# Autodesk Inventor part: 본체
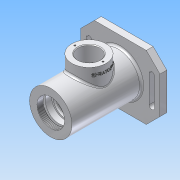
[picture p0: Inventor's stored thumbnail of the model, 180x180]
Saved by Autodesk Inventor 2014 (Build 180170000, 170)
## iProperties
Created: 2017-10
Part Number: 본체
Material: 알루미늄 6061
Document SubType Name: Modeling
Designer: user
Density: 2.71 g/cm^3
Appearance: 알루미늄 - 평지
Mass: 740.903 g
Surface Area: 653.463 cm^2
Volume: 273.396 cm^3
Author: user
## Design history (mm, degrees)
sketch "스케치1"
  geometry: C1 r 31 at (0, 0); 1 further point
  constraints: 1 centre point, 1 coincident
  dimensions: "d0" = 62 diameter of C1
extrude "돌출1" new body sketch "스케치1" distance "d1" = 102; taper "d2" = 0 deg
sketch "스케치2"
  geometry: L1 (-58, 47)-(58, 47); L2 (58, 47)-(58, -47); L3 (58, -47)-(-58, -47); L4 (-58, -47)-(-58, 47); L5 (-58, 0)-(58, 0); L6 (0, 47)-(0, -47); C1 r 31 at (0, 0) reference; 1 further point
  constraints: 12 end point, 5 midpoint, 2 parallel, 1 coincident, 1 horizontal, 1 perpendicular
  dimensions: "d3" = 116 distance of L2.end L3.end; "d4" = 94 distance of L1.end L2.end
extrude "돌출2" join sketch "스케치2" distance "d5" = 10; taper "d6" = 0 deg
sketch "스케치3"
  geometry: L1 (58, 47)-(-58, 47) reference; L2 (-58, -47)-(58, -47) reference; L3 (58, -47)-(58, 47) reference; L4 (0, 47)-(0, -47); L5 (58, 47)-(-58, 47) reference; L6 (-58, 47)-(-58, -47) reference; L7 (-58, -47)-(58, -47) reference; L8 (58, -47)-(58, 47) reference; L9 (-58, 0)-(58, 0); L10 (-46, 20)-(-46, -20); L11 (-46, 20)-(-46, -20); L12 (-50, 20)-(-50, -20); L13 (-42, -20)-(-42, 20); A1 r 4 centre (-46, 20) between (-42, 20) and (-50, 20); A2 r 4 centre (-46, -20) between (-50, -20) and (-42, -20); 3 further points
  constraints: 14 end point, 6 midpoint, 4 point on circle, 4 tangent, 2 centre point, 2 equal length, 1 perpendicular, 1 point on line
  dimensions: "d100" = 40 distance of L10.start L10.end; "d101" = 46 horizontal distance of point (0, 0) L10.end; "d102" = 8 diameter of A2
  node "투영된 루프1"
node "작업 평면1"
chamfer "모따기1" distance "d12" = 20; stored, may be unused: second distance "d13" = 2, angle "d14" = 45 deg
sketch "스케치4"
  geometry: C1 r 35 at (0, 0); 1 further point
  constraints: 1 centre point, 1 coincident
  dimensions: "d15" = 70 diameter of C1
extrude "돌출4" join sketch "스케치4" distance "d16" = 3; taper "d17" = 0 deg
node "작업 평면2"
sketch "스케치5"
  geometry: L1 (0, 0)-(-56, 0); C1 r 25 at (-56, 0)
  constraints: 2 end point, 1 centre point, 1 coincident, 1 horizontal
  dimensions: "d19" = 56 distance of L1.start L1.end; "d20" = 50 diameter of C1
extrude "돌출5" join sketch "스케치5" stored distance "d21" = 3; taper "d22" = 0 deg
sketch "스케치6"
  geometry: C1 r 31 at (0, 0) reference; 1 further point
  constraints: 1 coincident
hole "구멍1" sketch "스케치6" at (0, 0) diameter "d23" = 40.376; stored, may be unused: countersink angle "d27" = 90 deg, drill point angle "d29" = 0 deg; dims "d24" = 6, "d25" = 4, "d26" = 2, "d28" = 9
sketch "스케치7"
  geometry: C1 r 20.188 at (0, 0) reference; C2 r 24 at (0, 0)
  constraints: 1 centre point, 1 coincident
  dimensions: "d30" = 48 diameter of C2
extrude "돌출6" cut sketch "스케치7" distance "d31" = 3; taper "d32" = 0 deg
sketch "스케치8"
  geometry: C1 r 24 at (0, 0) reference; C2 r 20 at (0, 0)
  constraints: 1 centre point, 1 coincident
  dimensions: "d33" = 40 diameter of C2
extrude "돌출7" cut sketch "스케치8" distance "d34" = 9; taper "d35" = 0 deg
sketch "스케치9"
  geometry: C1 r 20 at (0, 0) reference; C2 r 17.5 at (0, 0)
  constraints: 1 centre point, 1 coincident
  dimensions: "d36" = 35 diameter of C2
extrude "돌출8" cut sketch "스케치9" distance "d37" = 3.25; taper "d38" = 0 deg
sketch "스케치10"
  geometry: C1 r 17.5 at (0, 0) reference; C2 r 18.5 at (0, 0)
  constraints: 1 centre point, 1 coincident
  dimensions: "d39" = 37 diameter of C2
extrude "돌출9" cut sketch "스케치10" distance "d40" = 1.75; taper "d41" = 0 deg
sketch "스케치11"
  geometry: C1 r 18.5 at (0, 0) reference; C2 r 17.5 at (0, 0)
  constraints: 1 centre point, 1 coincident
  dimensions: "d42" = 35 diameter of C2
extrude "돌출10" cut sketch "스케치11" distance "d43" = 11; taper "d44" = 0 deg
sketch "스케치12"
  geometry: C1 r 17.5 at (0, 0) reference; C2 r 26 at (0, 0)
  constraints: 1 centre point, 1 coincident
  dimensions: "d45" = 52 diameter of C2
extrude "돌출11" cut sketch "스케치12" distance "d46" = 38; taper "d47" = 0 deg
sketch "스케치13"
  geometry: L1 (115, -35)-(115, 35) reference; L2 (0, 0)-(115, 0); L3 (115, 0)-(101, 0); L4 (101, 0)-(101, -16); L5 (115, 0)-(115, -22); L6 (101, -16)-(115, -22)
  constraints: 10 end point, 2 point on line, 1 midpoint, 1 vertical
  dimensions: "d48" = 14 distance of L2.end L3.end; "d51" = 44 diameter of L5.end L2; "d52" = 32 diameter of L4.end L2
revolve "회전1" sketch "스케치13" stored, may be unused: angle "d53" = 90 deg
sketch "스케치14"
  geometry: C1 r 16 at (0, 0) reference; C2 r 12.5 at (0, 0)
  constraints: 1 centre point, 1 coincident
  dimensions: "d54" = 25 diameter of C2
extrude "돌출12" cut sketch "스케치14" distance "d55" = 7.3; taper "d56" = 0 deg
sketch "스케치15"
  geometry: C1 r 12.5 at (0, 0) reference; C2 r 10 at (0, 0)
  constraints: 1 centre point, 1 coincident
  dimensions: "d57" = 20 diameter of C2
extrude "돌출13" cut sketch "스케치15" distance "d58" = 2.7; taper "d59" = 0 deg
sketch "스케치16"
  geometry: C1 r 10 at (0, 0) reference; C2 r 16.5 at (0, 0)
  constraints: 1 centre point, 1 coincident
  dimensions: "d60" = 33 diameter of C2
extrude "돌출14" cut sketch "스케치16" distance "d61" = 5; taper "d62" = 0 deg
sketch "스케치17"
  geometry: C1 r 16.5 at (0, 0) reference; C2 r 17.5 at (0, 0)
  constraints: 1 centre point, 1 coincident
  dimensions: "d63" = 35 diameter of C2
extrude "돌출15" cut sketch "스케치17" distance "d64" = 11; taper "d65" = 0 deg
fillet "모깎기1" dims "d66" = 3
fillet "모깎기2" dims "d67" = 3, "d68" = 0.3
fillet "모깎기3" dims "d69" = 0.3
chamfer "모따기2" distance "d70" = 0.7; stored, may be unused: second distance "d71" = 2, angle "d72" = 30 deg
sketch "스케치18"
  geometry: C1 r 25 at (0, 0) reference; C2 r 16 at (0, 0); 1 further point
  constraints: 1 centre point, 1 coincident
  dimensions: "d73" = 32 diameter of C2
extrude "돌출16" cut sketch "스케치18" distance "d74" = 29.5; taper "d75" = 0 deg
sketch "스케치19" dims "d76" = 41
  geometry: L1 (0, 0)-(0, 20.5); C1 r 25 at (0, 0) reference; 2 further points
  constraints: 2 coincident, 2 end point, 1 vertical, 1 vertical alignment, 2 other
hole "구멍2" sketch "스케치19" at (0, 20.5) diameter "d77" = 2.459; stored, may be unused: countersink angle "d81" = 90 deg, drill point angle "d83" = 118 deg; dims "d78" = 6, "d79" = 4, "d80" = 2, "d82" = 8
node "작업축1"
chamfer "모따기3" distance "d87" = 1; stored, may be unused: second distance "d88" = 2, angle "d89" = 30 deg
fillet "모깎기4" dims "d90" = 3
node "작업 평면3"
sketch "스케치20"
  geometry: L1 (-81, -47)-(-31, -47) reference; L2 (0, -31)-(0, 31) reference; 2 further points
  constraints: 1 other
  dimensions: "d92" = 56 horizontal distance of point (-56, -37) L2.start; "d93" = 10 vertical distance of point (-56, -37) L1.start
feature "엠보싱1" sketch "스케치20" dims "d0" = 62, "d94" = 0.5, "d95" = 0
chamfer "모따기4" distance "d96" = 1; stored, may be unused: second distance "d97" = 2, angle "d98" = 30 deg
extrude "돌출17" cut sketch "스케치3" distance "d103" = 10; taper "d104" = 0 deg
node "작업 평면4"
node "솔리드1"
pattern_circular "원형 패턴1" dims angle "d85" = 360 deg
mirror "대칭2"
other parameters: "d18" = -47, "d91" = -25
